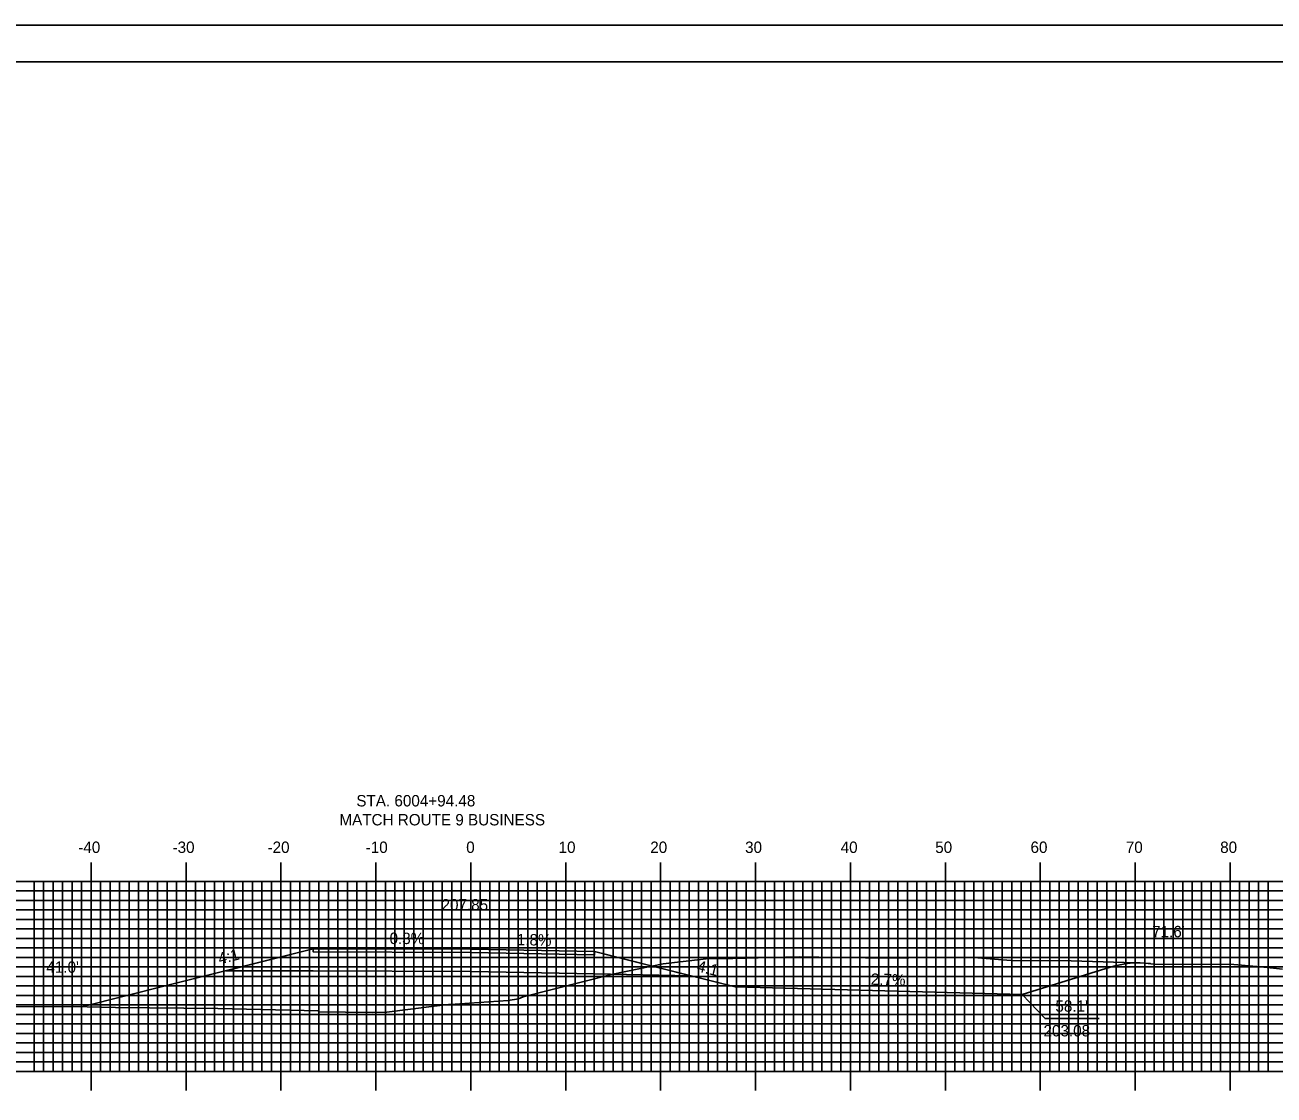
# Model space of a CAD drawing. Extents: x 852087 to 852430, y 366898 to 367118.
# Drawn here: x 852205.6 to 852337.2, y 367005.7 to 367118.4 of the extents above; entities that cross this region are included whole.
import ezdxf

# ---------------------------------------------------------------- set-up
doc = ezdxf.new("R2010")
doc.units = 0
for name, color, linetype in [('ANNOTATION', 7, 'Continuous'), ('BORDER', 7, 'Continuous'), ('D_Roadway_Centerline', 7, 'Continuous'), ('D_Roadway_Edge_TW', 7, 'Continuous'), ('D_Roadway_SlopeLines', 7, 'Continuous'), ('D_Roadway_SubGrade', 7, 'Continuous'), ('D_Text_Standard', 7, 'Continuous'), ('H_V ANNOTATION', 7, 'Continuous'), ('MAJOR', 7, 'Continuous'), ('MINOR', 7, 'Continuous'), ('PLOT BOUNDARY', 7, 'Continuous'), ('S_Roadway_Centerline', 7, 'Continuous')]:
    doc.layers.add(name, color=color, linetype=linetype)

msp = doc.modelspace()

# ---------------------------------------------------------------- linework, layer by layer
at = {"layer": 'ANNOTATION'}
msp.add_lwpolyline([(852318.72, 367013.71), (852313.03, 367013.71), (852310.63, 367016.24)], dxfattribs=at)
at = {"layer": 'BORDER'}
msp.add_lwpolyline([(852102.93, 366904.47), (852422.93, 366904.47), (852422.93, 367114.47), (852102.93, 367114.47)], close=True, dxfattribs=at)
at = {"layer": 'D_Roadway_Centerline'}
for p, q in [((852310.63, 367016.24), (852319.9, 367019.13)), ((852280.37, 367017.07), (852310.63, 367016.24))]:
    msp.add_line(p, q, dxfattribs=at)
msp.add_lwpolyline([(852265.57, 367020.77), (852269.57, 367019.77), (852280.37, 367017.07)], dxfattribs=at)
msp.add_arc((852322.88, 367009.58), 10, 82.7901, 107.3139, dxfattribs=at)
at = {"layer": 'D_Roadway_Edge_TW'}
msp.add_lwpolyline([(852235.93, 367020.73), (852235.93, 367021.06), (852252.53, 367021.01), (852265.57, 367020.77), (852265.57, 367020.43), (852252.53, 367020.67)], close=True, dxfattribs=at)
at = {"layer": 'D_Roadway_SlopeLines'}
msp.add_lwpolyline([(852235.93, 367021.06), (852220.63, 367017.24), (852211.54, 367014.97)], dxfattribs=at)
at = {"layer": 'D_Roadway_SubGrade'}
msp.add_line((852265.57, 367018.43), (852275.7, 367018.23), dxfattribs=at)
msp.add_lwpolyline([(852252.53, 367018.67), (852252.53, 367018.67), (852235.93, 367018.73), (852226.72, 367018.76), (852235.93, 367021.06), (852235.93, 367020.73), (852252.53, 367020.67), (852265.57, 367020.43), (852265.57, 367020.77), (852275.7, 367018.23), (852265.57, 367018.43)], close=True, dxfattribs=at)
at = {"layer": 'MAJOR'}
for p, q in [((852212.53, 367030.17), (852212.53, 367028.16)), ((852222.53, 367030.17), (852222.53, 367028.16)), ((852232.53, 367030.17), (852232.53, 367028.16)), ((852242.53, 367030.17), (852242.53, 367028.16)), ((852252.53, 367030.17), (852252.53, 367028.16)), ((852262.53, 367030.17), (852262.53, 367028.16)), ((852272.53, 367030.17), (852272.53, 367028.16)), ((852282.53, 367030.17), (852282.53, 367028.16)), ((852292.53, 367030.17), (852292.53, 367028.16)), ((852302.53, 367030.17), (852302.53, 367028.16)), ((852312.53, 367030.17), (852312.53, 367028.16)), ((852322.53, 367030.17), (852322.53, 367028.16)), ((852332.53, 367030.17), (852332.53, 367028.16)), ((852112.53, 367028.16), (852392.53, 367028.16)), ((852112.53, 367028.16), (852392.53, 367028.16)), ((852212.53, 367008.16), (852212.53, 367028.16)), ((852222.53, 367008.16), (852222.53, 367028.16)), ((852232.53, 367008.16), (852232.53, 367028.16)), ((852242.53, 367008.16), (852242.53, 367028.16)), ((852252.53, 367008.16), (852252.53, 367028.16)), ((852262.53, 367008.16), (852262.53, 367028.16)), ((852272.53, 367008.16), (852272.53, 367028.16)), ((852282.53, 367008.16), (852282.53, 367028.16)), ((852292.53, 367008.16), (852292.53, 367028.16)), ((852302.53, 367008.16), (852302.53, 367028.16)), ((852312.53, 367008.16), (852312.53, 367028.16)), ((852322.53, 367008.16), (852322.53, 367028.16)), ((852332.53, 367008.16), (852332.53, 367028.16)), ((852112.53, 367023.16), (852392.53, 367023.16)), ((852112.53, 367018.16), (852392.53, 367018.16)), ((852112.53, 367013.16), (852392.53, 367013.16)), ((852112.53, 367008.16), (852392.53, 367008.16)), ((852112.53, 367008.16), (852392.53, 367008.16)), ((852212.53, 367006.16), (852212.53, 367008.16)), ((852222.53, 367006.16), (852222.53, 367008.16)), ((852232.53, 367006.16), (852232.53, 367008.16)), ((852242.53, 367006.16), (852242.53, 367008.16)), ((852252.53, 367006.16), (852252.53, 367008.16)), ((852262.53, 367006.16), (852262.53, 367008.16)), ((852272.53, 367006.16), (852272.53, 367008.16)), ((852282.53, 367006.16), (852282.53, 367008.16)), ((852292.53, 367006.16), (852292.53, 367008.16)), ((852302.53, 367006.16), (852302.53, 367008.16)), ((852312.53, 367006.16), (852312.53, 367008.16)), ((852322.53, 367006.16), (852322.53, 367008.16)), ((852332.53, 367006.16), (852332.53, 367008.16))]:
    msp.add_line(p, q, dxfattribs=at)
at = {"layer": 'MINOR'}
for p, q in [((852206.53, 367008.16), (852206.53, 367028.16)), ((852207.53, 367008.16), (852207.53, 367028.16)), ((852208.53, 367008.16), (852208.53, 367028.16)), ((852209.53, 367008.16), (852209.53, 367028.16)), ((852210.53, 367008.16), (852210.53, 367028.16)), ((852211.53, 367008.16), (852211.53, 367028.16)), ((852213.53, 367008.16), (852213.53, 367028.16)), ((852214.53, 367008.16), (852214.53, 367028.16)), ((852215.53, 367008.16), (852215.53, 367028.16)), ((852216.53, 367008.16), (852216.53, 367028.16)), ((852217.53, 367008.16), (852217.53, 367028.16)), ((852218.53, 367008.16), (852218.53, 367028.16)), ((852219.53, 367008.16), (852219.53, 367028.16)), ((852220.53, 367008.16), (852220.53, 367028.16)), ((852221.53, 367008.16), (852221.53, 367028.16)), ((852223.53, 367008.16), (852223.53, 367028.16)), ((852224.53, 367008.16), (852224.53, 367028.16)), ((852225.53, 367008.16), (852225.53, 367028.16)), ((852226.53, 367008.16), (852226.53, 367028.16)), ((852227.53, 367008.16), (852227.53, 367028.16)), ((852228.53, 367008.16), (852228.53, 367028.16)), ((852229.53, 367008.16), (852229.53, 367028.16)), ((852230.53, 367008.16), (852230.53, 367028.16)), ((852231.53, 367008.16), (852231.53, 367028.16)), ((852233.53, 367008.16), (852233.53, 367028.16)), ((852234.53, 367008.16), (852234.53, 367028.16)), ((852235.53, 367008.16), (852235.53, 367028.16)), ((852236.53, 367008.16), (852236.53, 367028.16)), ((852237.53, 367008.16), (852237.53, 367028.16)), ((852238.53, 367008.16), (852238.53, 367028.16)), ((852239.53, 367008.16), (852239.53, 367028.16)), ((852240.53, 367008.16), (852240.53, 367028.16)), ((852241.53, 367008.16), (852241.53, 367028.16)), ((852243.53, 367008.16), (852243.53, 367028.16)), ((852244.53, 367008.16), (852244.53, 367028.16)), ((852245.53, 367008.16), (852245.53, 367028.16)), ((852246.53, 367008.16), (852246.53, 367028.16)), ((852247.53, 367008.16), (852247.53, 367028.16)), ((852248.53, 367008.16), (852248.53, 367028.16)), ((852249.53, 367008.16), (852249.53, 367028.16)), ((852250.53, 367008.16), (852250.53, 367028.16)), ((852251.53, 367008.16), (852251.53, 367028.16)), ((852253.53, 367008.16), (852253.53, 367028.16)), ((852254.53, 367008.16), (852254.53, 367028.16)), ((852255.53, 367008.16), (852255.53, 367028.16)), ((852256.53, 367008.16), (852256.53, 367028.16)), ((852257.53, 367008.16), (852257.53, 367028.16)), ((852258.53, 367008.16), (852258.53, 367028.16)), ((852259.53, 367008.16), (852259.53, 367028.16)), ((852260.53, 367008.16), (852260.53, 367028.16)), ((852261.53, 367008.16), (852261.53, 367028.16)), ((852263.53, 367008.16), (852263.53, 367028.16)), ((852264.53, 367008.16), (852264.53, 367028.16)), ((852265.53, 367008.16), (852265.53, 367028.16)), ((852266.53, 367008.16), (852266.53, 367028.16)), ((852267.53, 367008.16), (852267.53, 367028.16)), ((852268.53, 367008.16), (852268.53, 367028.16)), ((852269.53, 367008.16), (852269.53, 367028.16)), ((852270.53, 367008.16), (852270.53, 367028.16)), ((852271.53, 367008.16), (852271.53, 367028.16)), ((852273.53, 367008.16), (852273.53, 367028.16)), ((852274.53, 367008.16), (852274.53, 367028.16)), ((852275.53, 367008.16), (852275.53, 367028.16)), ((852276.53, 367008.16), (852276.53, 367028.16)), ((852277.53, 367008.16), (852277.53, 367028.16)), ((852278.53, 367008.16), (852278.53, 367028.16)), ((852279.53, 367008.16), (852279.53, 367028.16)), ((852280.53, 367008.16), (852280.53, 367028.16)), ((852281.53, 367008.16), (852281.53, 367028.16)), ((852283.53, 367008.16), (852283.53, 367028.16)), ((852284.53, 367008.16), (852284.53, 367028.16)), ((852285.53, 367008.16), (852285.53, 367028.16)), ((852286.53, 367008.16), (852286.53, 367028.16)), ((852287.53, 367008.16), (852287.53, 367028.16)), ((852288.53, 367008.16), (852288.53, 367028.16)), ((852289.53, 367008.16), (852289.53, 367028.16)), ((852290.53, 367008.16), (852290.53, 367028.16)), ((852291.53, 367008.16), (852291.53, 367028.16)), ((852293.53, 367008.16), (852293.53, 367028.16)), ((852294.53, 367008.16), (852294.53, 367028.16)), ((852295.53, 367008.16), (852295.53, 367028.16)), ((852296.53, 367008.16), (852296.53, 367028.16)), ((852297.53, 367008.16), (852297.53, 367028.16)), ((852298.53, 367008.16), (852298.53, 367028.16)), ((852299.53, 367008.16), (852299.53, 367028.16)), ((852300.53, 367008.16), (852300.53, 367028.16)), ((852301.53, 367008.16), (852301.53, 367028.16)), ((852303.53, 367008.16), (852303.53, 367028.16)), ((852304.53, 367008.16), (852304.53, 367028.16)), ((852305.53, 367008.16), (852305.53, 367028.16)), ((852306.53, 367008.16), (852306.53, 367028.16)), ((852307.53, 367008.16), (852307.53, 367028.16)), ((852308.53, 367008.16), (852308.53, 367028.16)), ((852309.53, 367008.16), (852309.53, 367028.16)), ((852310.53, 367008.16), (852310.53, 367028.16)), ((852311.53, 367008.16), (852311.53, 367028.16)), ((852313.53, 367008.16), (852313.53, 367028.16)), ((852314.53, 367008.16), (852314.53, 367028.16)), ((852315.53, 367008.16), (852315.53, 367028.16)), ((852316.53, 367008.16), (852316.53, 367028.16)), ((852317.53, 367008.16), (852317.53, 367028.16)), ((852318.53, 367008.16), (852318.53, 367028.16)), ((852319.53, 367008.16), (852319.53, 367028.16)), ((852320.53, 367008.16), (852320.53, 367028.16)), ((852321.53, 367008.16), (852321.53, 367028.16)), ((852323.53, 367008.16), (852323.53, 367028.16)), ((852324.53, 367008.16), (852324.53, 367028.16)), ((852325.53, 367008.16), (852325.53, 367028.16)), ((852326.53, 367008.16), (852326.53, 367028.16)), ((852327.53, 367008.16), (852327.53, 367028.16)), ((852328.53, 367008.16), (852328.53, 367028.16)), ((852329.53, 367008.16), (852329.53, 367028.16)), ((852330.53, 367008.16), (852330.53, 367028.16)), ((852331.53, 367008.16), (852331.53, 367028.16)), ((852333.53, 367008.16), (852333.53, 367028.16)), ((852334.53, 367008.16), (852334.53, 367028.16)), ((852335.53, 367008.16), (852335.53, 367028.16)), ((852336.53, 367008.16), (852336.53, 367028.16)), ((852112.53, 367027.16), (852392.53, 367027.16)), ((852112.53, 367026.16), (852392.53, 367026.16)), ((852112.53, 367025.16), (852392.53, 367025.16)), ((852112.53, 367024.16), (852392.53, 367024.16)), ((852112.53, 367022.16), (852392.53, 367022.16)), ((852112.53, 367021.16), (852392.53, 367021.16)), ((852112.53, 367020.16), (852392.53, 367020.16)), ((852112.53, 367019.16), (852392.53, 367019.16)), ((852112.53, 367017.16), (852392.53, 367017.16)), ((852112.53, 367016.16), (852392.53, 367016.16)), ((852112.53, 367015.16), (852392.53, 367015.16)), ((852112.53, 367014.16), (852392.53, 367014.16)), ((852112.53, 367012.16), (852392.53, 367012.16)), ((852112.53, 367011.16), (852392.53, 367011.16)), ((852112.53, 367010.16), (852392.53, 367010.16)), ((852112.53, 367009.16), (852392.53, 367009.16))]:
    msp.add_line(p, q, dxfattribs=at)
at = {"layer": 'PLOT BOUNDARY'}
msp.add_lwpolyline([(852086.74, 366898.35), (852426.74, 366898.35), (852426.74, 367118.35), (852086.74, 367118.35)], close=True, dxfattribs=at)
at = {"layer": 'S_Roadway_Centerline'}
msp.add_lwpolyline([(852196.71, 367014.91), (852210.64, 367014.98), (852215.1, 367014.89), (852225.89, 367014.79), (852236.49, 367014.55), (852236.54, 367014.43), (852242.13, 367014.36), (852243.69, 367014.4), (852248.66, 367015.02), (852250.2, 367015.19), (852250.36, 367015.21), (852256.47, 367015.62), (852257.57, 367015.78), (852258.04, 367015.99), (852267.5, 367018.41), (852272.81, 367019.49), (852276.42, 367019.9), (852277.33, 367020.02), (852280.15, 367020.03), (852284.15, 367020.14), (852287.2, 367020.21), (852291.25, 367020.16), (852294.1, 367020.12), (852298.67, 367020.12), (852305.48, 367020.14), (852309.45, 367019.84), (852315.8, 367019.81), (852323.6, 367019.57), (852324.45, 367019.46), (852325.54, 367019.43), (852332.53, 367019.46), (852335.74, 367019.15), (852337.11, 367019.03), (852338.04, 367018.91)], dxfattribs=at)

# ---------------------------------------------------------------- texts
at = {"layer": 'ANNOTATION'}
for s, p in [('    STA. 6004+94.48', (852238.69, 367036.06)), ('MATCH ROUTE 9 BUSINESS', (852238.69, 367034.06)), ("58.1' ", (852314.12, 367014.44)), ('203.08', (852312.87, 367011.84))]:
    msp.add_text(s, height=1.2, dxfattribs=at).set_placement(p)
for s, rotation, p in [('0.3%', 359.811, (852243.97, 367021.57)), ('1.8%', 358.9408, (852257.37, 367021.45)), ('4:1', 14.0351, (852226.08, 367019.42)), ('4:1', 345.9638, (852276.28, 367018.71)), ('2.7%', 358.4271, (852294.66, 367017.28))]:
    msp.add_text(s, height=1.2, rotation=rotation, dxfattribs=at).set_placement(p)
at = {"layer": 'D_Roadway_Centerline'}
for s, p in [('C', (852252.53, 367021.01)), ('L', (852252.53, 367021))]:
    msp.add_text(s, height=0.0146, dxfattribs=at).set_placement(p)
at = {"layer": 'D_Text_Standard'}
for s, p in [("71.6'", (852324.31, 367022.28)), ("41.0'", (852207.82, 367018.54))]:
    msp.add_text(s, height=1.2, dxfattribs=at).set_placement(p)
at = {"layer": 'H_V ANNOTATION'}
for s, p in [('-40', (852211.18, 367031.16)), ('-30', (852221.11, 367031.16)), ('-20', (852231.12, 367031.16)), ('-10', (852241.46, 367031.16)), ('0', (852252.05, 367031.16)), ('10', (852261.78, 367031.16)), ('20', (852271.44, 367031.16)), ('30', (852281.43, 367031.16)), ('40', (852291.5, 367031.16)), ('50', (852301.46, 367031.16)), ('60', (852311.5, 367031.16)), ('70', (852321.54, 367031.16)), ('80', (852331.48, 367031.16)), ('207.85', (852249.45, 367025.1))]:
    msp.add_text(s, height=1.2, dxfattribs=at).set_placement(p)
at = {"layer": 'S_Roadway_Centerline'}
for s, p in [('C', (852305.47, 367020.14)), ('C', (852305.47, 367020.14)), ('L', (852305.48, 367020.13)), ('L', (852305.48, 367020.13))]:
    msp.add_text(s, height=0.0146, dxfattribs=at).set_placement(p)

doc.saveas('drawing.dxf')
